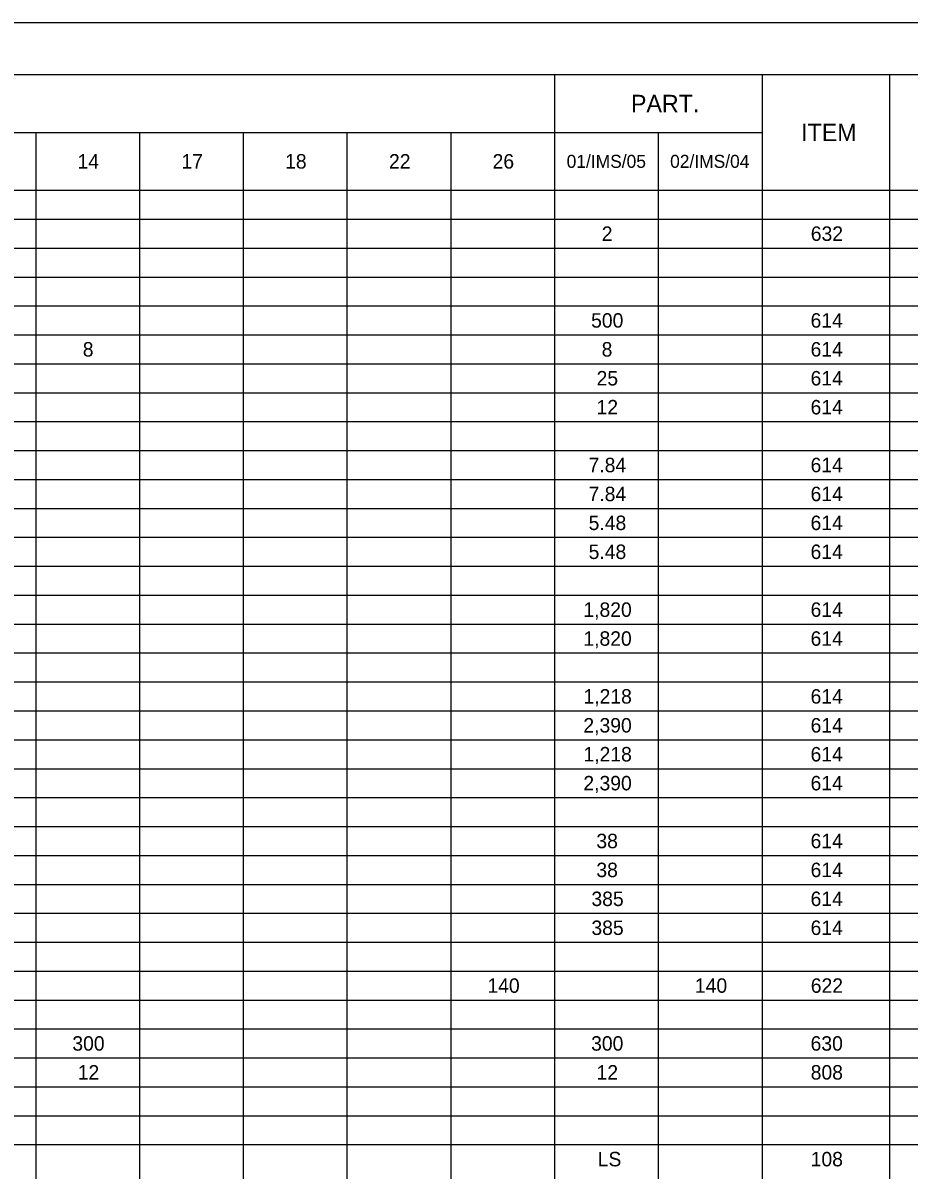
# Model space of a CAD drawing. Extents: x -32.2 to 34, y 0 to 22.
# Drawn here: x 8.41 to 16.99, y 10.89 to 22 of the extents above; entities that cross this region are included whole.
import ezdxf

# ---------------------------------------------------------------- set-up
doc = ezdxf.new("R2010")
doc.units = 0
for name, color, linetype in [('SH_Border', 7, 'Continuous'), ('SH_Cut_Line', 7, 'Continuous'), ('SH_Text', 7, 'Continuous')]:
    doc.layers.add(name, color=color, linetype=linetype)

msp = doc.modelspace()

# ---------------------------------------------------------------- linework, layer by layer
at = {"layer": 'SH_Border'}
msp.add_lwpolyline([(1.5, 21.5), (33.5, 21.5), (33.5, 0.5), (1.5, 0.5)], close=True, dxfattribs=at)
at = {"layer": 'SH_Cut_Line'}
msp.add_lwpolyline([(0, 0), (34, 0), (34, 22), (0, 22)], close=True, dxfattribs=at)
at = {"layer": 'SH_Text'}
for p, q in [((1.5, 21.5), (32.004, 21.5)), ((13.556, 21.5), (13.556, 0.5)), ((15.566, 21.5), (15.566, 0.5)), ((16.801, 21.5), (16.801, 0.5)), ((1.5, 20.94), (15.566, 20.94)), ((8.533, 20.94), (8.533, 0.5)), ((9.538, 20.94), (9.538, 0.5)), ((10.542, 20.94), (10.542, 0.5)), ((11.547, 20.94), (11.547, 0.5)), ((12.552, 20.94), (12.552, 0.5)), ((14.561, 20.94), (14.561, 0.5)), ((1.5, 20.38), (32.004, 20.38)), ((1.5, 20.1), (32.004, 20.1)), ((1.5, 19.82), (32.004, 19.82)), ((1.5, 19.54), (32.004, 19.54)), ((1.5, 19.26), (32.004, 19.26)), ((1.5, 18.98), (32.004, 18.98)), ((1.5, 18.7), (32.004, 18.7)), ((1.5, 18.42), (32.004, 18.42)), ((1.5, 18.14), (32.004, 18.14)), ((1.5, 17.86), (32.004, 17.86)), ((1.5, 17.58), (32.004, 17.58)), ((1.5, 17.3), (32.004, 17.3)), ((1.5, 17.02), (32.004, 17.02)), ((1.5, 16.74), (32.004, 16.74)), ((1.5, 16.46), (32.004, 16.46)), ((1.5, 16.18), (32.004, 16.18)), ((1.5, 15.9), (32.004, 15.9)), ((1.5, 15.62), (32.004, 15.62)), ((1.5, 15.34), (32.004, 15.34)), ((1.5, 15.06), (32.004, 15.06)), ((1.5, 14.78), (32.004, 14.78)), ((1.5, 14.5), (32.004, 14.5)), ((1.5, 14.22), (32.004, 14.22)), ((1.5, 13.94), (32.004, 13.94)), ((1.5, 13.66), (32.004, 13.66)), ((1.5, 13.38), (32.004, 13.38)), ((1.5, 13.1), (32.004, 13.1)), ((1.5, 12.82), (32.004, 12.82)), ((1.5, 12.54), (32.004, 12.54)), ((1.5, 12.26), (32.004, 12.26)), ((1.5, 11.98), (32.004, 11.98)), ((1.5, 11.7), (32.004, 11.7)), ((1.5, 11.42), (32.004, 11.42)), ((1.5, 11.14), (32.004, 11.14))]:
    msp.add_line(p, q, dxfattribs=at)

# ---------------------------------------------------------------- texts
for s, height, p in [('PART.', 0.168, (14.297, 21.136)), ('ITEM', 0.168, (15.945, 20.856)), ('14', 0.14, (8.938, 20.59)), ('17', 0.14, (9.944, 20.59)), ('18', 0.14, (10.948, 20.59)), ('22', 0.14, (11.954, 20.59)), ('26', 0.14, (12.957, 20.59)), ('01/IMS/05', 0.126, (13.674, 20.597)), ('02/IMS/04', 0.126, (14.676, 20.597)), ('2', 0.14, (14.014, 19.89)), ('632', 0.14, (16.038, 19.89)), ('500', 0.14, (13.911, 19.05)), ('614', 0.14, (16.036, 19.05)), ('8', 0.14, (8.989, 18.77)), ('8', 0.14, (14.013, 18.77)), ('614', 0.14, (16.036, 18.77)), ('25', 0.14, (13.964, 18.49)), ('614', 0.14, (16.036, 18.49)), ('12', 0.14, (13.964, 18.21)), ('614', 0.14, (16.036, 18.21)), ('7.84', 0.14, (13.886, 17.65)), ('614', 0.14, (16.036, 17.65)), ('7.84', 0.14, (13.886, 17.37)), ('614', 0.14, (16.036, 17.37)), ('5.48', 0.14, (13.887, 17.09)), ('614', 0.14, (16.036, 17.09)), ('5.48', 0.14, (13.887, 16.81)), ('614', 0.14, (16.036, 16.81)), ('1,820', 0.14, (13.836, 16.25)), ('614', 0.14, (16.036, 16.25)), ('1,820', 0.14, (13.836, 15.97)), ('614', 0.14, (16.036, 15.97)), ('1,218', 0.14, (13.837, 15.41)), ('614', 0.14, (16.036, 15.41)), ('2,390', 0.14, (13.836, 15.13)), ('614', 0.14, (16.036, 15.13)), ('1,218', 0.14, (13.837, 14.85)), ('614', 0.14, (16.036, 14.85)), ('2,390', 0.14, (13.836, 14.57)), ('614', 0.14, (16.036, 14.57)), ('38', 0.14, (13.962, 14.01)), ('614', 0.14, (16.036, 14.01)), ('38', 0.14, (13.962, 13.73)), ('614', 0.14, (16.036, 13.73)), ('385', 0.14, (13.914, 13.45)), ('614', 0.14, (16.036, 13.45)), ('385', 0.14, (13.914, 13.17)), ('614', 0.14, (16.036, 13.17)), ('140', 0.14, (12.907, 12.61)), ('140', 0.14, (14.916, 12.61)), ('622', 0.14, (16.038, 12.61)), ('300', 0.14, (8.888, 12.05)), ('300', 0.14, (13.911, 12.05)), ('630', 0.14, (16.036, 12.05)), ('12', 0.14, (8.94, 11.77)), ('12', 0.14, (13.964, 11.77)), ('808', 0.14, (16.037, 11.77)), ('LS', 0.14, (13.975, 10.93)), ('108', 0.14, (16.037, 10.93))]:
    msp.add_text(s, height=height, dxfattribs=at).set_placement(p)

doc.saveas('drawing.dxf')
